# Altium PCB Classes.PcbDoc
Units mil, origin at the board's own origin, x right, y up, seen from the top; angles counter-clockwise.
Board outline 6000 x 4000 mil, 4 copper layers (Top Layer, Int1 (GND), Int2 (PWR), Bottom Layer), stack 43.712 mil thick; 12 components, 7 nets, 21 pads, 0 vias.
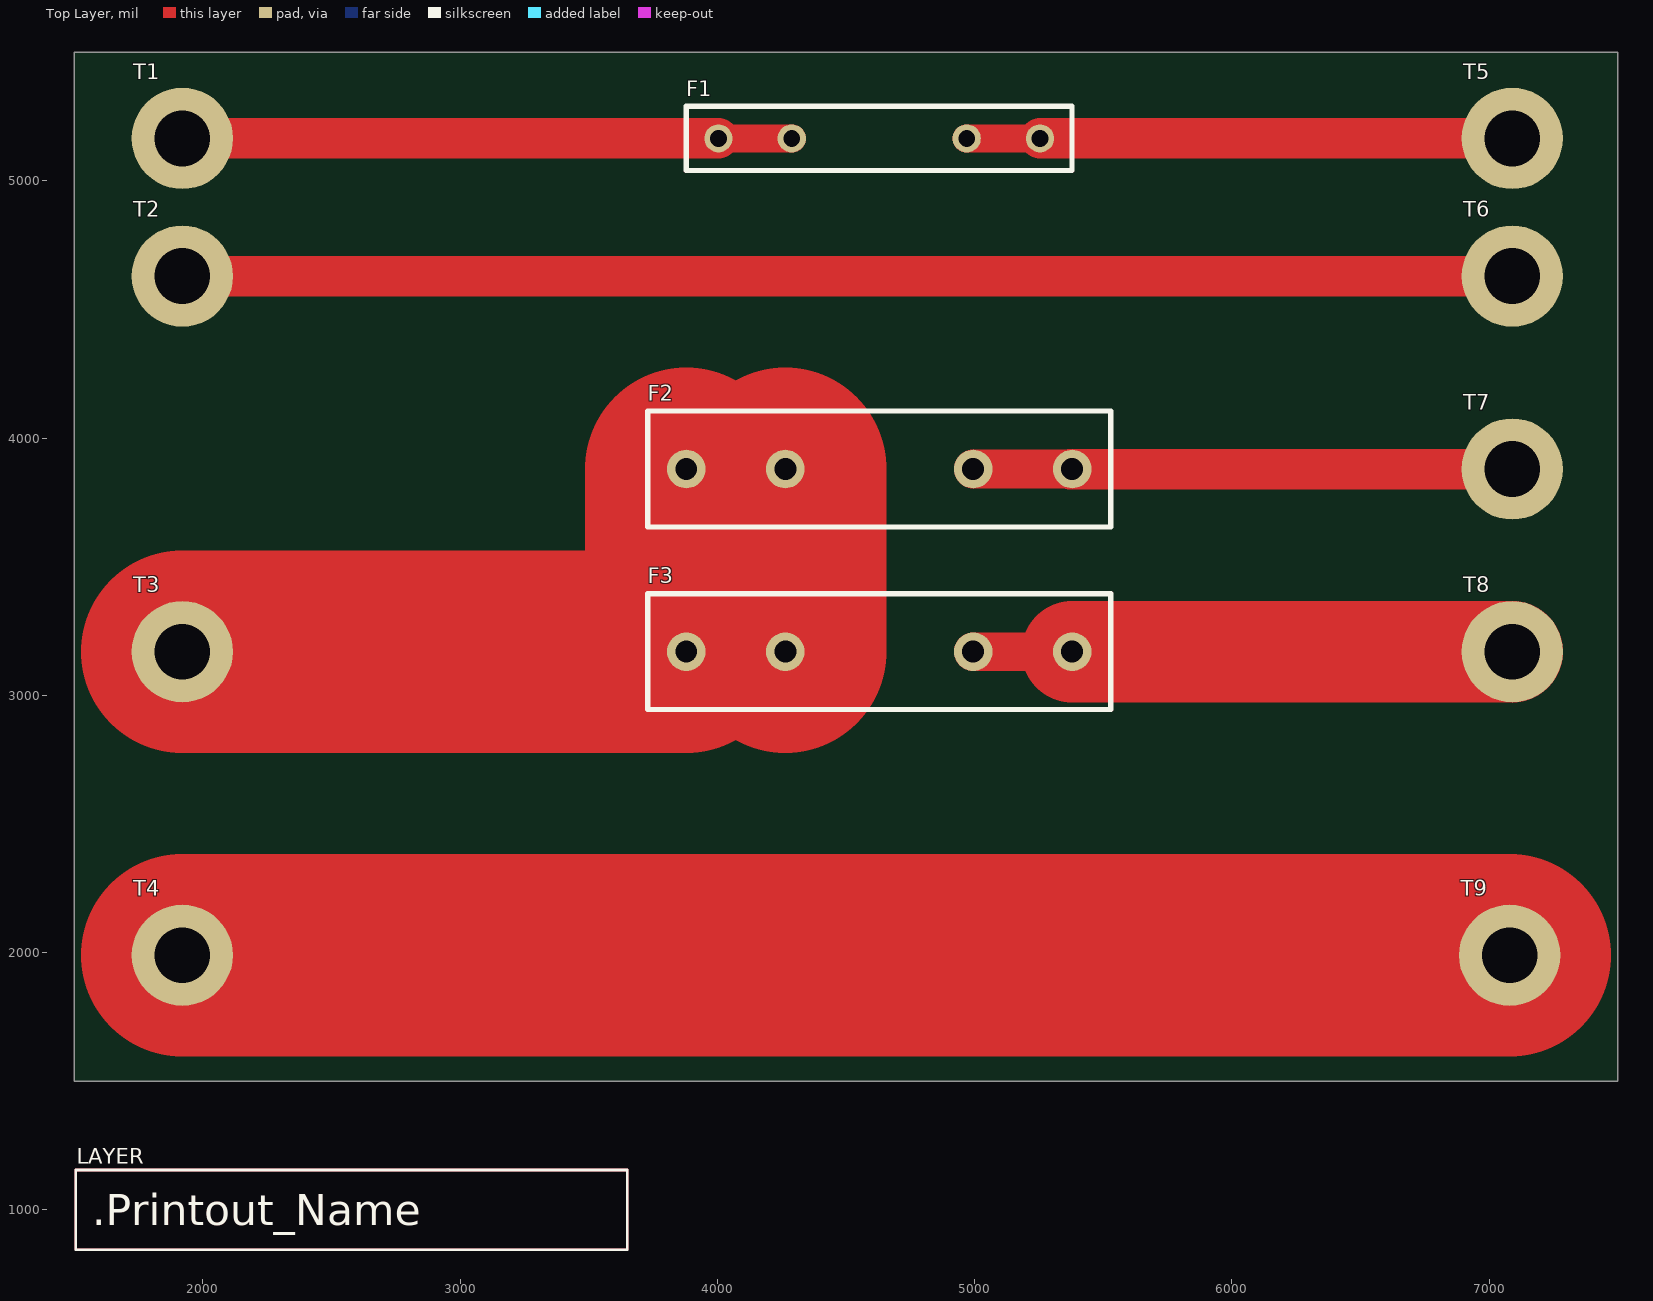
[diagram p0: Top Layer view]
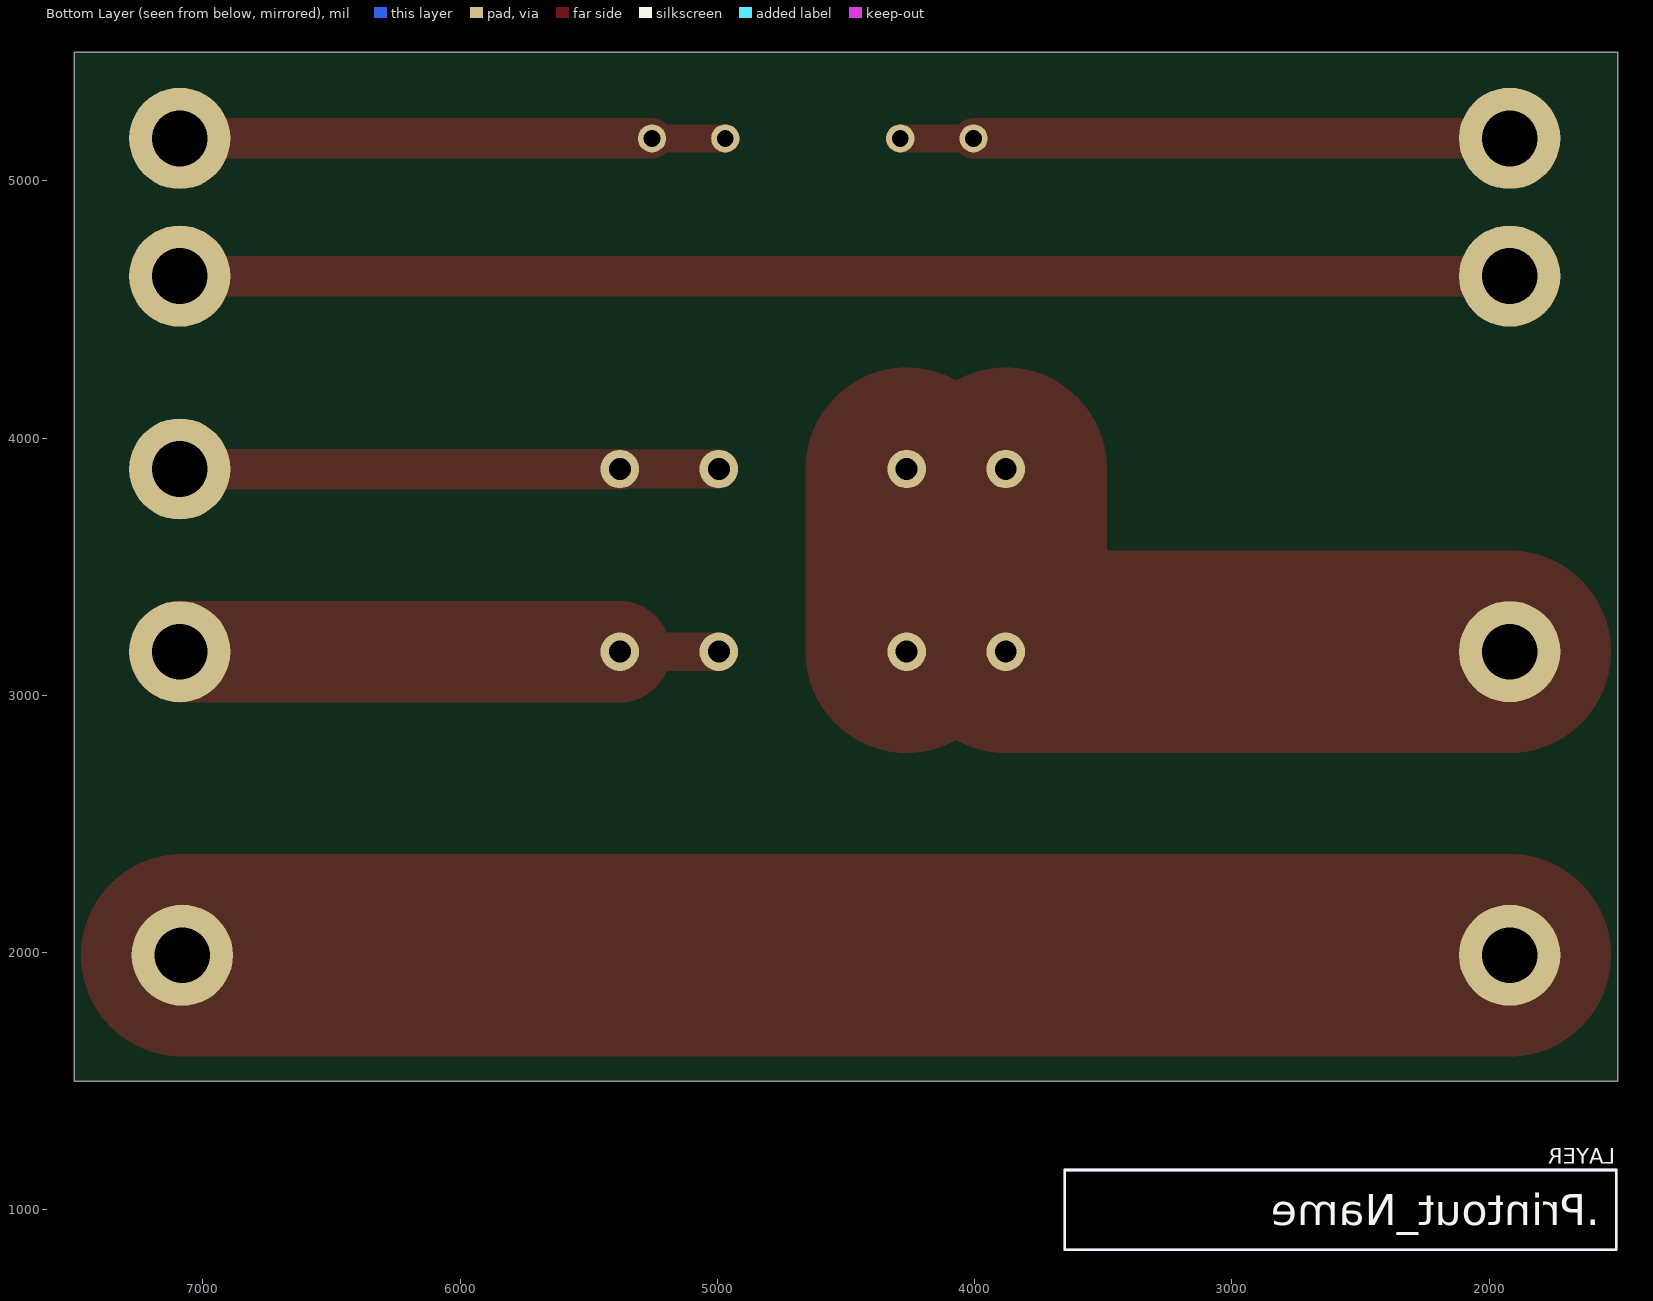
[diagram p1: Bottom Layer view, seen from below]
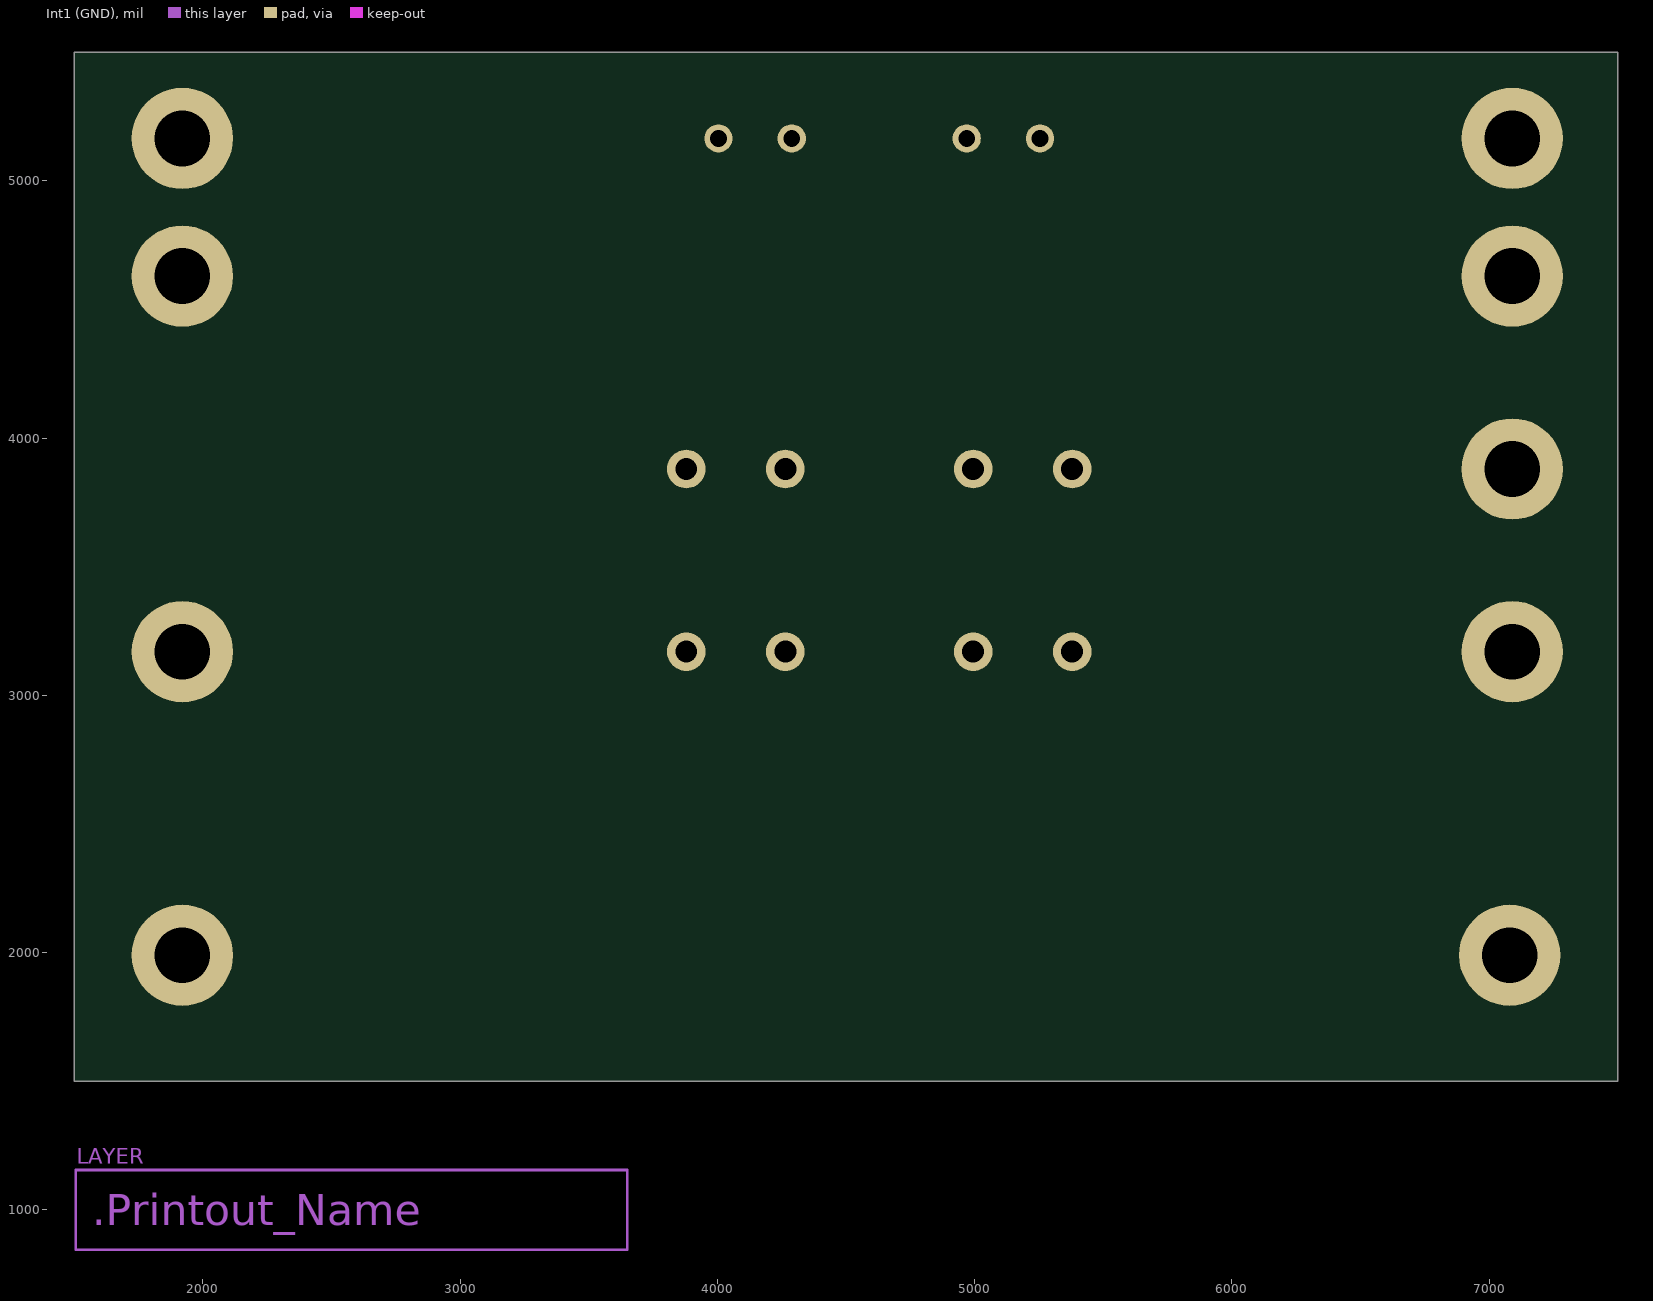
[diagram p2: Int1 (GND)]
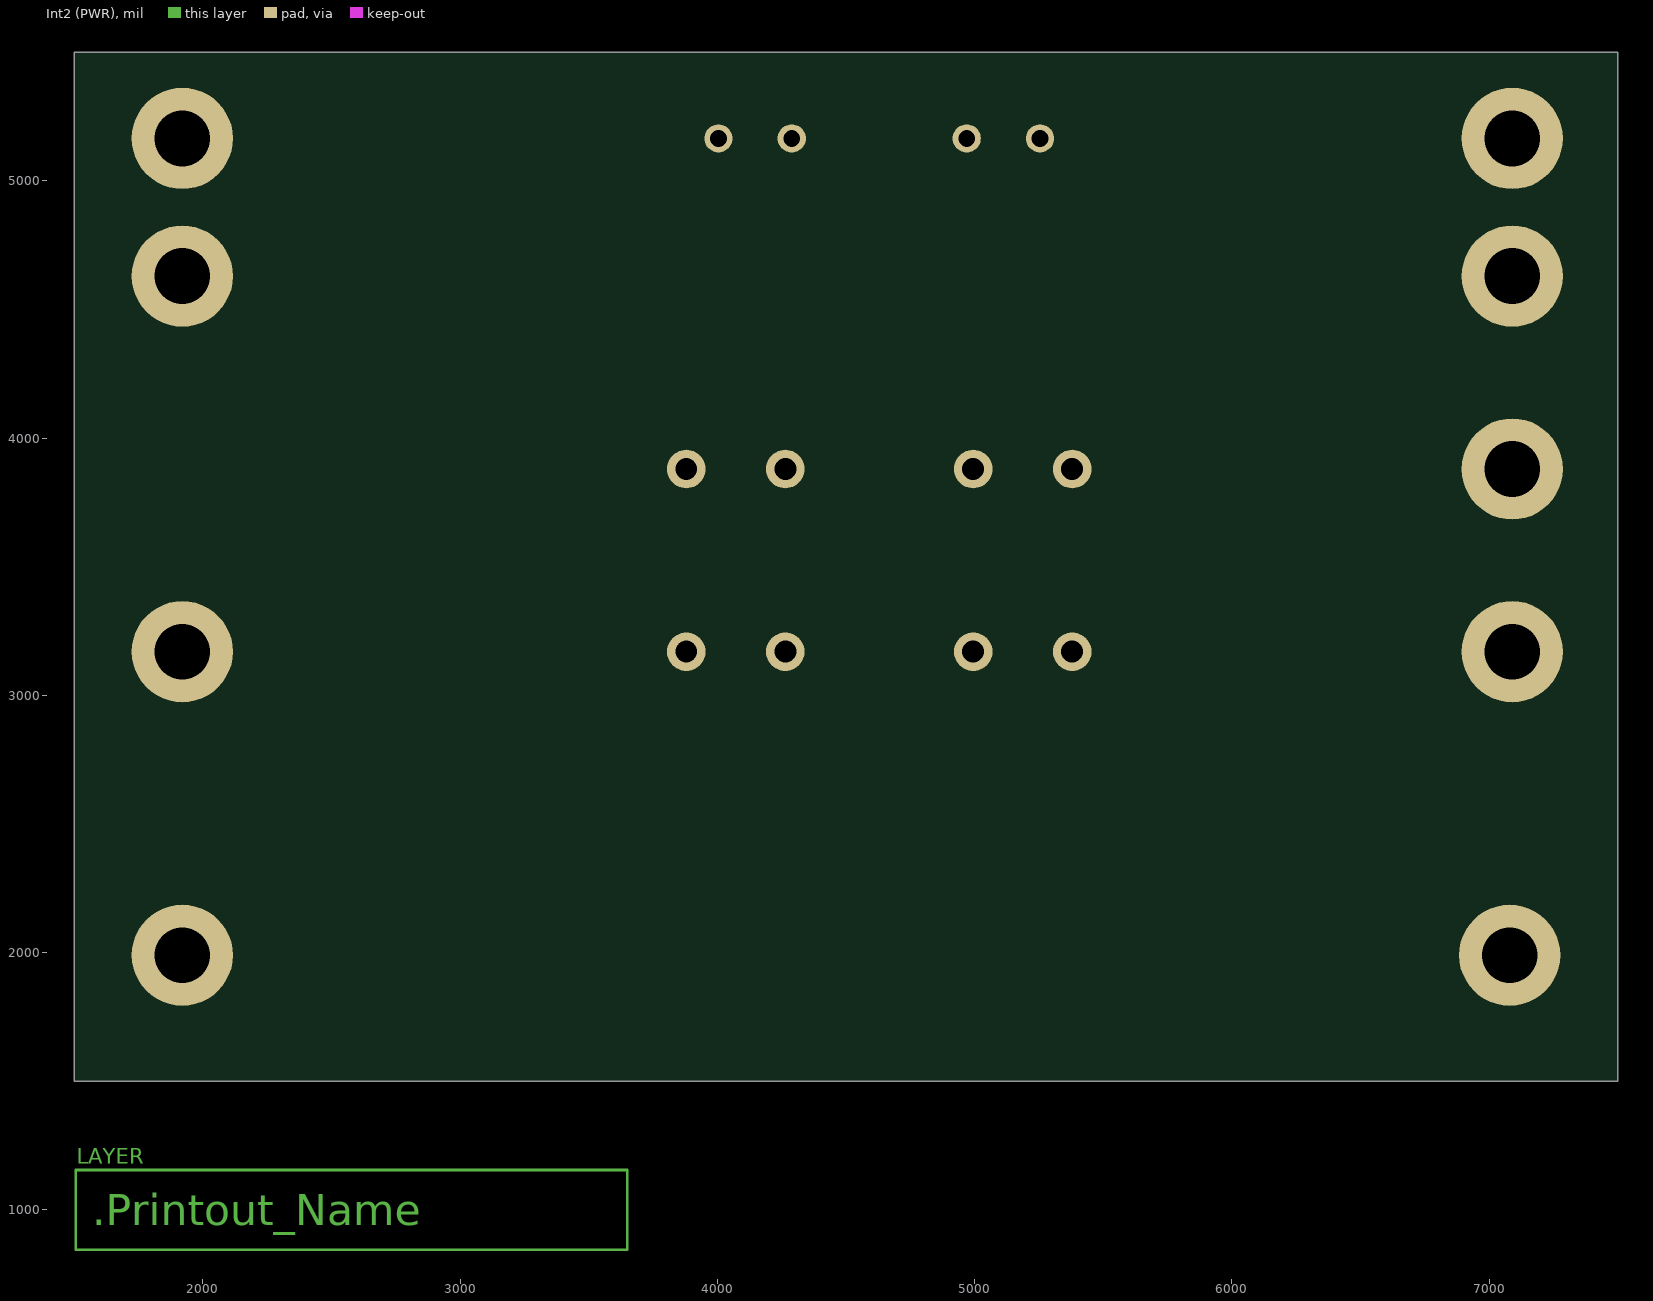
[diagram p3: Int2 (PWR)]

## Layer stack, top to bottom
Top Solder: solder mask 1, SM-001, Dk 4
Top Layer: signal copper 1.378
Dielectric 1: prepreg 5.1, PP-017, Dk 4.3
Int1 (GND): signal copper 1.378
Dielectric 3: core 28, Core-039, Dk 4.8
Int2 (PWR): signal copper 1.378
Dielectric 5: prepreg 5.1, PP-017, Dk 4.3
Bottom Layer: signal copper 1.378
Bottom Solder: solder mask 1, SM-001, Dk 4

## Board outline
1500,1500 1500,5500 7500,5500 7500,1500

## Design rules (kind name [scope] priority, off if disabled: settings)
Clearance 240_VOLT [InNetClass('VOLT_240')] p1: gap=252 ignorepadtopadclearanceinfootprint=FALSE except(0: Arc-Hole Track-Hole SMDPad-Hole THPad-Hole Via-Hole Fill-Hole Poly-Hole Region-Hole Text-Hole)
Clearance 120_VOLT [InNetClass('VOLT_120')] p2: gap=126 ignorepadtopadclearanceinfootprint=FALSE except(0: Arc-Hole Track-Hole SMDPad-Hole THPad-Hole Via-Hole Fill-Hole Poly-Hole Region-Hole Text-Hole)
Clearance 50_VOLT [InNetClass('VOLT_50')] p3: gap=25 ignorepadtopadclearanceinfootprint=FALSE except(0: Arc-Hole Track-Hole SMDPad-Hole THPad-Hole Via-Hole Fill-Hole Poly-Hole Region-Hole Text-Hole)
Clearance Clearance_ALL [All] p4: gap=10 ignorepadtopadclearanceinfootprint=FALSE except(0: Arc-Hole Track-Hole SMDPad-Hole THPad-Hole Via-Hole Fill-Hole Poly-Hole Region-Hole Text-Hole)
MinimumAnnularRing [All] p1: minimumring=10
PlaneConnect PlaneVia [IsVia] p1: planeconnectstyle=Direct reliefexpansion=20 reliefentries=4 reliefconductorwidth=10 reliefairgap=10
PlaneConnect [All] p2: planeconnectstyle=Relief reliefexpansion=20 reliefentries=4 reliefconductorwidth=10 reliefairgap=10
PolygonConnect PolygonVia [IsVia] p1: connectstyle=Direct reliefconductorwidth=10 reliefentries=4 polygonreliefangle="90 Angle" airgapwidth=10
PolygonConnect [All] p2: connectstyle=Relief reliefconductorwidth=10 reliefentries=4 polygonreliefangle="90 Angle" airgapwidth=10
RoutingVias [All] p1: holewidth=28 width=50 viastyle="Through Hole" minholewidth=28 minwidth=50 maxholewidth=28 maxwidth=50
SMDNeckDown [All] p1: percent=100.000
SilkToSolderMaskClearance SilkscreenOverComponentPads [IsPad] p1: minsilkscreentomaskgap=10 clearancetoexposedcopper=TRUE
SolderMaskExpansion [All] p1: expansion=4 istentingtop=FALSE
Width 5_AMP [InNetClass('AMP_5')] p1: maxlimit=59.06 minlimit=59.06 preferedwidth=59.06
Width 30_AMP [InNetClass('AMP_30')] p2: maxlimit=787.4 minlimit=787.4 preferedwidth=787.4
Width 20_AMP [InNetClass('AMP_20')] p3: maxlimit=393.7 minlimit=393.7 preferedwidth=393.7
Width 10_AMP [InNetClass('AMP_10')] p4: maxlimit=157.48 minlimit=157.48 preferedwidth=157.48
Width 1_AMP [InNetClass('AMP_1')] p5: maxlimit=9.84 minlimit=9.84 preferedwidth=9.84
Width Width_ALL [All] p6: maxlimit=10 minlimit=10 preferedwidth=10
28 further rules are at their usual default settings.

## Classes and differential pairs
component class Fuse: F1 F2 F3
net class TrainingClass: NetF1_1 NetT2_1
component class Right: T5 T6 T7 T8 T9
component class Left: T1 T2 T3 T4
component class 240_VOLT: F2 F3
component class 120_VOLT: F1
net class VOLT_240: NetF2_1 NetF2_2 NetF3_2 NetT4_1
net class VOLT_120: NetF1_1 NetF1_2 NetT2_1
net class AMP_10: NetF1_1 NetF1_2 NetF2_2 NetT2_1
net class AMP_30: NetF2_1 NetT4_1
net class AMP_20: NetF3_2

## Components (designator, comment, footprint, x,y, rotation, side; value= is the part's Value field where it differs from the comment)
F1 "10 A" "1/4 FUSE" 4004.2,5165.06 r0 top
F2 "10 A" "13/32 FUSE"#1 3879.2,3880 r0 top
F3 "20 A" "13/32 FUSE"#2 3879.2,3170 r0 top
T1 "M5 SCREW TERMINAL" "M5 TERMINAL" 1920,5165.06 r0 top
T2 "M5 SCREW TERMINAL" "M5 TERMINAL" 1920,4630 r0 top
T3 "M5 SCREW TERMINAL" "M5 TERMINAL" 1920,3170 r0 top
T4 "M5 SCREW TERMINAL" "M5 TERMINAL" 1920,1990 r0 top
T5 "M5 SCREW TERMINAL" "M5 TERMINAL" 7090,5165.06 r90 top
T6 "M5 SCREW TERMINAL" "M5 TERMINAL" 7090,4630 r90 top
T7 "M5 SCREW TERMINAL" "M5 TERMINAL" 7090,3880 r90 top
T8 "M5 SCREW TERMINAL" "M5 TERMINAL" 7090,3170 r90 top
T9 "M5 SCREW TERMINAL" "M5 TERMINAL" 7080,1990 r90 top

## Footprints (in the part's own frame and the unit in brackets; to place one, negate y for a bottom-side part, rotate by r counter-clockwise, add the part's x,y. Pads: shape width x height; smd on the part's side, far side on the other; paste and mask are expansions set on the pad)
"1/4 FUSE" [mil]
  round 110 hole 65: 1(0,0) 1(285,0) 2(965,0) 2(1250,0)
  Top Layer lines w110: 0,0 285,0 ; 965,0 1250,0
  silkscreen extent -125,-125 1375,125
"13/32 FUSE"#1 [mil]
  round 150 hole 85: 1(0,0) 1(385,0) 2(1115,0) 2(1500,0)
  Top Layer lines w150: 5,0 375,0 385,0 ; 1115,0 1490,0
  silkscreen extent -150,-225 1650,225
"13/32 FUSE"#2 [mil]
  round 150 hole 85: 1(0,0) 1(385,0) 2(1115,0) 2(1500,0)
  Top Layer lines w150: 5,0 385,0 ; 1115,0 1490,0
  silkscreen extent -150,-225 1650,225
"M5 TERMINAL" [mm]
  round 10 hole 5.5: 1(0,0)

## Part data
F1: library part "10 AMP 250 VAC FUSE", "10 AMP 250 VAC FUSE", MANUFACTURE="COOPER BUSSMAN", PART NUMBER=GBB-10-R, VOLTAGE_RATING="250 VAC"
F2: library part "10 AMP 600 VAC FUSE", "10 AMP 600 VAC FUSE", MANUFACTURE="COOPER BUSSMAN", PART NUMBER=KTK-R-10, VOLTAGE_RATING="600 VAC"
F3: library part "20 AMP 600 VAC FUSE", "20 AMP 600 VAC FUSE", MANUFACTURE="COOPER BUSSMAN", PART NUMBER=KTK-R-20, VOLTAGE_RATING="600 VAC"
T1 T2 T3 T4 T5 T6 T7 T8 T9: library part TERMINAL

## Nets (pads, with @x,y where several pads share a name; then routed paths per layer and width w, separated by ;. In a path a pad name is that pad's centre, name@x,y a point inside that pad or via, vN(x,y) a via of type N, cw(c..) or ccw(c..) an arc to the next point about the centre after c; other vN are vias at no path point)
NetF1_1: F1.1 T1.1 | length 2084.2
  Top Layer w157.48: T1.1 F1.1@4004.2,5165.06
NetF1_2: F1.2 T5.1 | length 1835.8
  Top Layer w157.48: F1.2@5254.2,5165.06 T5.1
NetF2_1: F2.1 F3.1 T3.1 | length 3379.2
  Top Layer w787.4: T3.1 3879.2,3170 F2.1@3879.2,3880 ; F3.1@4264.2,3170 F2.1@4264.2,3880
NetF2_2: F2.2 T7.1 | length 1717.7
  Top Layer w157.48: F2.2@5372.34,3880 5379.2,3880 T7.1
NetF3_2: F3.2 T8.1 | length 1710.8
  Top Layer w393.7: F3.2@5379.2,3170 T8.1
NetT2_1: T2.1 T6.1 | length 5170
  Top Layer w157.48: T2.1 T6.1
NetT4_1: T4.1 T9.1 | length 5160
  Top Layer w787.4: T4.1 T9.1
copper on no net: | length 19640
  Top Layer w10: 1505,845 3650,845 3650,1155 1505,1155 1505,845
  Int1 (GND) w10: 1505,845 3650,845 3650,1155 1505,1155 1505,845
  Int2 (PWR) w10: 1505,845 3650,845 3650,1155 1505,1155 1505,845
  Bottom Layer w10: 1505,845 3650,845 3650,1155 1505,1155 1505,845

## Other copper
Top Layer:
  text "LAYER" at 1510,1180 h60
  text ".Printout_Name" at 1570,940 h120
Int1 (GND):
  text "LAYER" at 1510,1180 h60
  text ".Printout_Name" at 1570,940 h120
Int2 (PWR):
  text "LAYER" at 1510,1180 h60
  text ".Printout_Name" at 1570,940 h120
Bottom Layer:
  text "LAYER" at 1510,1180 h60
  text ".Printout_Name" at 1570,940 h120
Multi-Layer:
  lines w10: 1505,845 3650,845 3650,1155 1505,1155 1505,845
  text "LAYER" at 1510,1180 h60
  text ".Printout_Name" at 1570,940 h120

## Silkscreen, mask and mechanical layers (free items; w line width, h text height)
Top Overlay:
  lines w10: 1505,845 3650,845 3650,1155 1505,1155 1505,845
  text "LAYER" at 1510,1180 h60
  text ".Printout_Name" at 1570,940 h120
Bottom Overlay:
  lines w10: 1505,845 3650,845 3650,1155 1505,1155 1505,845
  text "LAYER" at 1510,1180 h60
  text ".Printout_Name" at 1570,940 h120
Top Paste:
  lines w10: 1505,845 3650,845 3650,1155 1505,1155 1505,845
  text "LAYER" at 1510,1180 h60
  text ".Printout_Name" at 1570,940 h120
Bottom Paste:
  lines w10: 1505,845 3650,845 3650,1155 1505,1155 1505,845
  text "LAYER" at 1510,1180 h60
  text ".Printout_Name" at 1570,940 h120
Top Solder:
  lines w10: 1505,845 3650,845 3650,1155 1505,1155 1505,845
  text "LAYER" at 1510,1180 h60
  text ".Printout_Name" at 1570,940 h120
Bottom Solder:
  lines w10: 1505,845 3650,845 3650,1155 1505,1155 1505,845
  text "LAYER" at 1510,1180 h60
  text ".Printout_Name" at 1570,940 h120
Drill Guide:
  lines w10: 1505,845 3650,845 3650,1155 1505,1155 1505,845
  text "LAYER" at 1510,1180 h60
  text ".Printout_Name" at 1570,940 h120
BOARD_OUTLINE:
  the board outline again, w10
TITLE_BLOCK:
  drawing of 99 lines, arcs and shapes, not listed
  text "1" at 1231.34,9370 h70
  text "2" at 3727,9370 h70
  text "3" at 6216.34,9370 h70
  text "4" at 8723.01,9370 h70
  text "5" at 11222,9370 h70
  text "6" at 13727,9370 h70
  text "DWG. NO." at 11320,9365 h30
  text "REV:" at 12330,9365 h30
  text ".PCB_DWG_NO" at 11535,9325 h25
  text ".PCB_REV" at 12345,9325 h25
  text "REVISIONS" at 12640,9195 h60
  text "ZONE" at 11055,9070 h60
  text "REV" at 11385,9070 h60
  text "DATE" at 13805,9070 h60
  text "DESCRIPTION" at 12400,9065 h60
  text "APPROVED" at 14310,9065 h60
  text "0" at 11415,8935 h60
  text "ORIGINAL" at 12475,8935 h60
  text "A" at 75,8227 h70
  text "A" at 14875,8227 h70
  text "B" at 75,5847 h70
  text "B" at 14875,5847 h70
  text "C" at 75,3472 h70
  text "C" at 14875,3472 h70
  text "DWG. NO." at 14865,2875 h30 r270
  text ".PCB_DWG_NO" at 14825,2660 h25 r270
  text "REV:" at 14865,1865 h30 r270
  text ".PCB_REV" at 14825,1850 h25 r270
  text "PART NO." at 8850,1810 h45
  text ".PCB_PART_NUMBER" at 9165,1810 h45
  text "CONTRACT NO.:" at 10220,1710 h70
  text "UNLESS OTHERWISE SPECIFIED DIMENSIONS" at 8870,1705 h45
  text "3207 GREY HAWK COURT" at 13605,1700 h45
  text "AND TOLERANCE ARE IN INCHES AND" at 8925,1630 h45
  text "SUITE 100" at 13605,1610 h45
  text "APPLY TO THE FINISHED PART" at 9035,1560 h45
  text "CARLSBAD, CA 92010" at 13605,1519.99 h45
  text ".CONTRACT_NUMBER" at 10455,1495 h100
  text "TOLERANCE ON:" at 9275,1435 h45
  text "USA" at 13605,1430 h45
  text "2 DEC. PLACE" at 8870,1345 h40
  text "3 DEC. PLACE" at 9325,1345 h40
  text "ANGLES" at 9860,1345 h40
  text "DESIGNER:" at 10220,1325 h45
  text "DATE:" at 11290,1325 h45
  text "TITLE:" at 11720,1325 h45
  text ".PCB_2_DEC_TOL" at 8925,1190 h60
  text ".PCB_3_DEC_TOL" at 9360,1190 h60
  text ".PCB_ANG_TOL" at 9825,1190 h60
  text ".PCB_TITLE_1" at 11895,1175 h100
  text "D" at 75,1102 h70
  text "D" at 14875,1102 h70
  text "ENGINEER:" at 10220,1090 h45
  text "DATE:" at 11290,1090 h45
  text "MATERIAL:" at 8870,1030 h45
  text ".PCB_TITLE_2" at 11890,880 h100
  text "CHECKER:" at 10220,850 h45
  text "DATE:" at 11290,850 h45
  text "QA:" at 10220,610 h45
  text "DATE:" at 11290,610 h45
  text "SIZE:" at 11780,590 h45
  text "CAGE CODE:" at 12025,590 h45
  text "DWG NO:" at 13025,590 h45
  text "REV:" at 14585,590 h45
  text "DATE:" at 8870,570 h45
  text ".PRINT_DATE" at 8920,450 h70
  text ".PCB_DWG_NO" at 13335,450 h100
  text "B" at 11820,445 h100
  text ".PCB_REV" at 14615,445 h100
  text ".CAGE_CODE" at 12195,435 h100
  text "PROJECT ENGINEER:" at 10220,370 h45
  text "DATE:" at 11290,370 h45
  text "FILE NAME:" at 8870,345 h45
  text "SCALE:" at 11720,275 h45
  text "SHEET:" at 13965,275 h45
  text ".PCB_FILE_NAME_NO_PATH" at 8920,225 h65
  text ".PCB_SCALE" at 11990,225 h60
  text "-" at 14275,225 h45
  text "OF" at 14415,225 h45
  text "-" at 14575,225 h45
  text "1" at 1231.34,70 h70
  text "2" at 3727,70 h70
  text "3" at 6216.34,70 h70
  text "4" at 8723.01,70 h70
  text "5" at 11222,70 h70
  text "6" at 13727,70 h70
Drill Drawing:
  circle w10: c7068.05,7363.33 r33.33
  lines w10: 1505,845 3650,845 3650,1155 1505,1155 1505,845 ; 7034.72,7029.99 7101.38,7029.99 7101.38,7096.66 7034.72,7096.66 7034.72,7029.99 ; 7034.72,7246.66 7101.38,7246.66 7068.05,7179.99 7034.72,7246.66
  lines w15: 6974.93,6984.99 13681.09,6984.99 ; 6974.93,7434.99 13681.09,7434.99 ; 7525.8,6834.99 7525.8,7584.99 ; 8055.67,6834.99 8055.67,7584.99 ; 9225.32,6834.99 9225.32,7584.99 ; 9731.2,6834.99 9731.2,7584.99 ; 10465,6834.99 10465,7584.99 ; 11964.55,6834.99 11964.55,7584.99 ; 12554.4,6834.99 12554.4,7584.99 ; 6974.93,6834.99 13681.09,6834.99 13681.09,7584.99 6974.93,7584.99 6974.93,6834.99
  text "Symbol" at 7064.93,7479.99 h72
  text "Count" at 7570.8,7479.99 h72
  text "Hole Size" at 8100.67,7479.99 h72
  text "Plated" at 9270.32,7479.99 h72
  text "Hole Type" at 9776.2,7479.99 h72
  text "Drill Layer Pair" at 10510,7479.99 h72
  text "Via/Pad" at 12009.55,7479.99 h72
  text "Hole Tolerance" at 12599.4,7479.99 h72
  text "4" at 7570.8,7329.99 h60
  text "65,00mil (1,651mm)" at 8100.67,7329.99 h60
  text "PTH" at 9270.32,7329.99 h60
  text "Round" at 9776.2,7329.99 h60
  text "Top Layer - Bottom Layer" at 10510,7329.99 h60
  text "Pad" at 12009.55,7329.99 h60
  text "8" at 7570.8,7179.99 h60
  text "85,00mil (2,159mm)" at 8100.67,7179.99 h60
  text "PTH" at 9270.32,7179.99 h60
  text "Round" at 9776.2,7179.99 h60
  text "Top Layer - Bottom Layer" at 10510,7179.99 h60
  text "Pad" at 12009.55,7179.99 h60
  text "9" at 7570.8,7029.99 h60
  text "216,54mil (5,500mm)" at 8100.67,7029.99 h60
  text "PTH" at 9270.32,7029.99 h60
  text "Round" at 9776.2,7029.99 h60
  text "Top Layer - Bottom Layer" at 10510,7029.99 h60
  text "Pad" at 12009.55,7029.99 h60
  text "21 Total" at 7570.8,6879.99 h60
  text "LAYER" at 1510,1180 h60
  text ".Printout_Name" at 1570,940 h120
CONTINUATION_BLOCK:
  region: 200,4750 130,4750 130,4700
  region: 200,4750 130,4750 130,4800
  region: 14800,4750 14870,4750 14870,4800
  region: 14800,4750 14870,4750 14870,4700
  region: 7500,200 7500,130 7550,130
  region: 7500,200 7500,130 7450,130
  region: 7500,9300 7500,9370 7450,9370
  region: 7500,9300 7500,9370 7550,9370
  lines w5: 0,2375 200,2375 ; 0,4750 200,4750 ; 0,7125 200,7125 ; 2500,0 2500,200 ; 2500,9300 2500,9500 ; 5000,0 5000,200 ; 5000,9300 5000,9500 ; 7500,0 7500,200 ; 7500,9300 7500,9500 ; 10000,0 10000,200 ; 10000,9300 10000,9500 ; 10300,200 14800,200 ; 11005,8775 14798,8775 ; 11005,8905 14798,8905 ; 11005,9035 14798,9035 ; 11005,9165 14798,9165 ; 11005,9295 11005,8645 14798,8645 ; 11305,8645 11305,9165 ; 11305,9300 11305,9395 12415,9395 12415,9300 ; 11605,8645 11605,9165 ; 11695,200 11695,350 ; 12000,350 12000,665 ; 12300,200 12300,350 ; 12305,9300 12305,9395 ; 12500,0 12500,200 ; 12500,9300 12500,9500 ; 13000,350 13000,665 ; 13605,8645 13605,9165 ; 13940,200 13940,350 ; 14205,8645 14205,9165 ; 14500,350 14500,665 ; 14800,350 11695,350 ; 14800,665 11695,665 11695,350 ; 14800,1400 14800,200 ; 14800,2375 15000,2375 ; 14800,4750 15000,4750 ; 14800,7125 15000,7125 ; 14800,200 200,200 200,9300 14800,9300 14800,200 ; 0,0 15000,0 15000,9500 0,9500 0,0
  text "1" at 1231.34,9370 h70
  text "2" at 3727,9370 h70
  text "3" at 6216.34,9370 h70
  text "4" at 8723.01,9370 h70
  text "5" at 11222,9370 h70
  text "6" at 13727,9370 h70
  text "DWG. NO." at 11320,9365 h30
  text "REV:" at 12330,9365 h30
  text ".PCB_DWG_NO" at 11535,9325 h25
  text ".PCB_REV" at 12345,9325 h25
  text "REVISIONS" at 12640,9195 h60
  text "ZONE" at 11055,9070 h60
  text "REV" at 11385,9070 h60
  text "DATE" at 13805,9070 h60
  text "DESCRIPTION" at 12400,9065 h60
  text "APPROVED" at 14310,9065 h60
  text "0" at 11415,8935 h60
  text "ORIGINAL" at 12475,8935 h60
  text "A" at 75,8227 h70
  text "A" at 14875,8227 h70
  text "B" at 75,5847 h70
  text "B" at 14875,5847 h70
  text "C" at 75,3472 h70
  text "C" at 14875,3472 h70
  text "D" at 75,1102 h70
  text "D" at 14875,1102 h70
  text "SIZE:" at 11780,590 h45
  text "CAGE CODE:" at 12025,590 h45
  text "DWG NO:" at 13025,590 h45
  text "REV:" at 14585,590 h45
  text ".PCB_DWG_NO" at 13335,450 h100
  text "B" at 11820,445 h100
  text ".PCB_REV" at 14615,445 h100
  text ".CAGE_CODE" at 12195,435 h100
  text "SCALE:" at 11720,275 h45
  text "SHEET:" at 13965,275 h45
  text ".PCB_SCALE" at 11990,225 h60
  text "-" at 14275,225 h45
  text "OF" at 14415,225 h45
  text "-" at 14575,225 h45
  text "1" at 1231.34,70 h70
  text "2" at 3727,70 h70
  text "3" at 6216.34,70 h70
  text "4" at 8723.01,70 h70
  text "5" at 11222,70 h70
  text "6" at 13727,70 h70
